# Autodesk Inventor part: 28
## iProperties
Created: 2011-12
Part Number: 28
Document SubType Name: Modeling
Designer: D Cole
Density: 1 g/cm^3
Author: D Cole
Translation Standard: STEP AP214IS
File Name: P:\Fastrack\53972_CRANE 3D\Press Fit\HATTERSLEY\100LS-PF\28MM\28.stp
Preprocessor: Autodesk Inventor 2008
Postprocessor: Build: 342, Release: 2008 SP3 - Date: Tue 05/27/2008
Sent Units: MILLIMETERS
Uncertainty: 0.01
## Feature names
1. Base1
